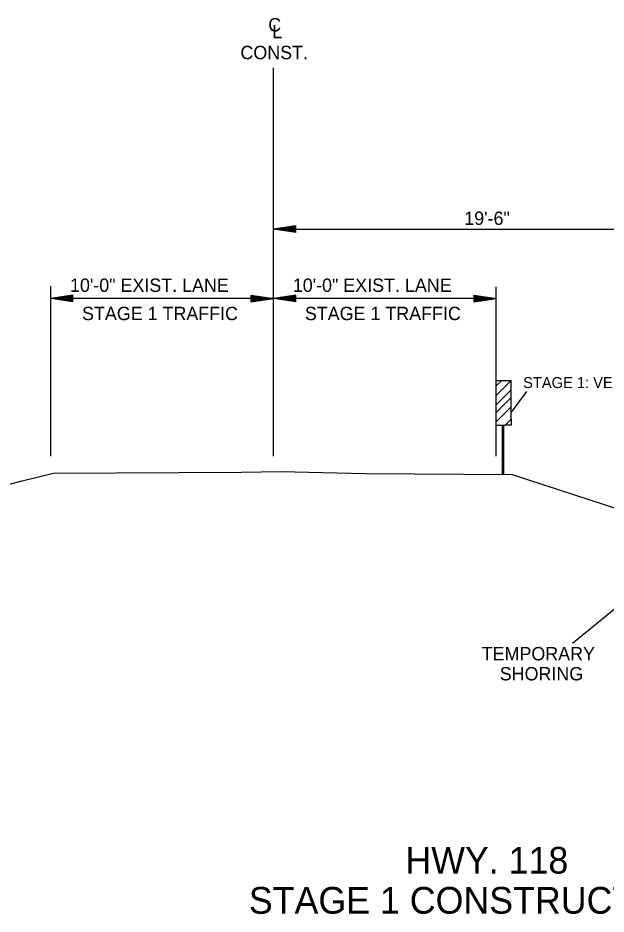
# Model space of a CAD drawing. Extents: x 2829243 to 2838161, y 467639 to 474695.
# Drawn here: x 2833675.1 to 2833939.1, y 469690.2 to 470092.4 of the extents above; entities that cross this region are included whole.
import ezdxf

# ---------------------------------------------------------------- set-up
doc = ezdxf.new("R2010")
doc.units = 0
for name, color, linetype in [('R_Dimension', 7, 'Continuous'), ('R_Draft', 7, 'Continuous'), ('R_Exist Surface', 7, 'Continuous'), ('R_MOT', 7, 'Continuous')]:
    doc.layers.add(name, color=color, linetype=linetype)

msp = doc.modelspace()

# ---------------------------------------------------------------- linework, layer by layer
at = {"layer": 'R_Dimension'}
for p, q in [((2833789.82, 469895.7), (2833789.82, 470070.05)), ((2833799.82, 469999.05), (2833789.82, 469997.55)), ((2833799.82, 469998.8), (2833791.49, 469997.55)), ((2833799.82, 469996.05), (2833799.82, 469999.05)), ((2833799.82, 469996.05), (2833789.82, 469997.55)), ((2833789.82, 469997.55), (2833984.82, 469997.55)), ((2833799.82, 469996.3), (2833791.49, 469997.55)), ((2833799.82, 469998.54), (2833793.21, 469997.55)), ((2833799.82, 469996.55), (2833793.21, 469997.55)), ((2833799.82, 469998.29), (2833794.88, 469997.55)), ((2833799.82, 469996.8), (2833794.88, 469997.55)), ((2833799.82, 469998.04), (2833796.57, 469997.55)), ((2833799.82, 469997.06), (2833796.57, 469997.55)), ((2833799.82, 469997.78), (2833798.24, 469997.55)), ((2833799.82, 469997.31), (2833798.24, 469997.55)), ((2833689.82, 469895.7), (2833689.82, 469971.96)), ((2833889.82, 469895.7), (2833889.82, 469971.71)), ((2833699.82, 469967.96), (2833689.82, 469966.46)), ((2833699.82, 469967.71), (2833691.49, 469966.46)), ((2833699.82, 469967.46), (2833693.21, 469966.46)), ((2833699.82, 469967.21), (2833694.88, 469966.46)), ((2833699.82, 469966.95), (2833696.57, 469966.46)), ((2833699.82, 469966.7), (2833698.24, 469966.46)), ((2833699.82, 469964.96), (2833699.82, 469967.96)), ((2833779.82, 469967.96), (2833789.82, 469966.46)), ((2833779.82, 469964.96), (2833779.82, 469967.96)), ((2833779.82, 469967.71), (2833788.15, 469966.46)), ((2833779.82, 469967.46), (2833786.43, 469966.46)), ((2833779.82, 469967.21), (2833784.77, 469966.46)), ((2833779.82, 469966.95), (2833783.07, 469966.46)), ((2833779.82, 469966.7), (2833781.4, 469966.46)), ((2833799.82, 469967.96), (2833789.82, 469966.46)), ((2833799.82, 469967.71), (2833791.49, 469966.46)), ((2833799.82, 469967.46), (2833793.21, 469966.46)), ((2833799.82, 469967.21), (2833794.88, 469966.46)), ((2833799.82, 469966.95), (2833796.57, 469966.46)), ((2833799.82, 469966.7), (2833798.24, 469966.46)), ((2833799.82, 469964.96), (2833799.82, 469967.96)), ((2833879.82, 469967.96), (2833889.82, 469966.46)), ((2833879.82, 469964.96), (2833879.82, 469967.96)), ((2833879.82, 469967.71), (2833888.15, 469966.46)), ((2833879.82, 469967.46), (2833886.43, 469966.46)), ((2833879.82, 469967.21), (2833884.77, 469966.46)), ((2833879.82, 469966.95), (2833883.07, 469966.46)), ((2833879.82, 469966.7), (2833881.4, 469966.46)), ((2833789.82, 469966.46), (2833689.82, 469966.46)), ((2833699.82, 469964.96), (2833689.82, 469966.46)), ((2833699.82, 469965.21), (2833691.49, 469966.46)), ((2833699.82, 469965.47), (2833693.21, 469966.46)), ((2833699.82, 469965.72), (2833694.88, 469966.46)), ((2833699.82, 469965.98), (2833696.57, 469966.46)), ((2833699.82, 469966.23), (2833698.24, 469966.46)), ((2833779.82, 469964.96), (2833789.82, 469966.46)), ((2833779.82, 469965.98), (2833783.07, 469966.46)), ((2833779.82, 469965.47), (2833786.43, 469966.46)), ((2833779.82, 469965.21), (2833788.15, 469966.46)), ((2833779.82, 469965.72), (2833784.77, 469966.46)), ((2833779.82, 469966.23), (2833781.4, 469966.46)), ((2833889.82, 469966.46), (2833789.82, 469966.46)), ((2833799.82, 469964.96), (2833789.82, 469966.46)), ((2833799.82, 469965.21), (2833791.49, 469966.46)), ((2833799.82, 469965.47), (2833793.21, 469966.46)), ((2833799.82, 469965.72), (2833794.88, 469966.46)), ((2833799.82, 469965.98), (2833796.57, 469966.46)), ((2833799.82, 469966.23), (2833798.24, 469966.46)), ((2833879.82, 469964.96), (2833889.82, 469966.46)), ((2833879.82, 469965.98), (2833883.07, 469966.46)), ((2833879.82, 469965.47), (2833886.43, 469966.46)), ((2833879.82, 469965.21), (2833888.15, 469966.46)), ((2833879.82, 469965.72), (2833884.77, 469966.46)), ((2833879.82, 469966.23), (2833881.4, 469966.46)), ((2833903.41, 469924.78), (2833896.53, 469915.42)), ((2833946.9, 469830.39), (2833923.98, 469811.61))]:
    msp.add_line(p, q, dxfattribs=at)
at = {"layer": 'R_Exist Surface'}
msp.add_lwpolyline([(2833628.82, 469872.05), (2833676.98, 469884.59), (2833691.04, 469888.03), (2833775.51, 469888.48), (2833793.11, 469888.86), (2833830.98, 469888.02), (2833896.92, 469887.46), (2833952.04, 469869.57), (2833960.07, 469866.18), (2833991.33, 469861.67), (2834079.18, 469822.7), (2834191.24, 469796.57), (2834240.84, 469792.36), (2834294.16, 469787.03), (2834384.57, 469777.66), (2834458.96, 469770.53), (2834481.01, 469772.31), (2834554.28, 469778.2), (2834608.3, 469785.59)], dxfattribs=at)
at = {"layer": 'R_MOT'}
for p, q in [((2833889.82, 469929.69), (2833892.29, 469929.69)), ((2833892.29, 469929.69), (2833889.82, 469927.26)), ((2833889.82, 469927.26), (2833889.82, 469929.69)), ((2833889.82, 469923.02), (2833896.53, 469929.69)), ((2833889.82, 469909.63), (2833889.82, 469927.26)), ((2833892.29, 469929.69), (2833896.53, 469929.69)), ((2833896.53, 469912.34), (2833896.53, 469929.69)), ((2833896.53, 469925.48), (2833889.82, 469918.81)), ((2833889.82, 469918.81), (2833889.82, 469923.02)), ((2833896.53, 469922.07), (2833889.82, 469915.39)), ((2833896.53, 469917.9), (2833896.53, 469922.07)), ((2833889.82, 469911.21), (2833896.53, 469917.9)), ((2833893.82, 469909.63), (2833896.53, 469912.34)), ((2833896.53, 469912.34), (2833896.53, 469909.63)), ((2833889.82, 469909.63), (2833893.82, 469909.63)), ((2833892.64, 469887.49), (2833892.64, 469909.46)), ((2833893.16, 469887.49), (2833893.16, 469909.46)), ((2833896.53, 469909.63), (2833893.82, 469909.63))]:
    msp.add_line(p, q, dxfattribs=at)

# ---------------------------------------------------------------- texts
at = {"layer": 'R_Dimension'}
for s, p in [('C', (2833787.47, 470086.34)), ('L', (2833789.28, 470083.28)), ('CONST.', (2833774.99, 470073.9)), ('19\'-6"', (2833875.44, 469999.51)), ('10\'-0" EXIST. LANE', (2833698.5, 469969.46)), ('10\'-0" EXIST. LANE', (2833798.5, 469969.46)), ('STAGE 1 TRAFFIC', (2833703.91, 469956.78)), ('STAGE 1 TRAFFIC', (2833803.91, 469956.78)), ('TEMPORARY', (2833883.27, 469804.08)), ('SHORING', (2833891.37, 469795.08))]:
    msp.add_text(s, height=6, dxfattribs=at).set_placement(p)
at = {"layer": 'R_Draft'}
for s, height, p in [('STAGE 1: VERTICAL PANEL', 4.9184, (2833901.86, 469926.3)), ('HWY. 118', 12, (2833849.02, 469708.37)), ('STAGE 1 CONSTRUCTION', 12, (2833778.76, 469690.37))]:
    msp.add_text(s, height=height, dxfattribs=at).set_placement(p)

doc.saveas('drawing.dxf')
